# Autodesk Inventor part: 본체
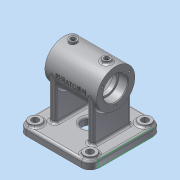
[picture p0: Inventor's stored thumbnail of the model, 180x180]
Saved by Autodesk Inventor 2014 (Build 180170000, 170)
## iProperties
Created: 2025-10
Part Number: 본체
Material: 알루미늄 6061
Document SubType Name: Modeling
Designer: dg
Density: 2.71 g/cm^3
Appearance: 알루미늄 - 평지
Mass: 505.532 g
Surface Area: 499.638 cm^2
Volume: 186.543 cm^3
Author: dg
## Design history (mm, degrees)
sketch "스케치1"
  geometry: L1 (-47, -47)-(47, -47); L2 (47, -47)-(47, 47); L3 (47, 47)-(-47, 47); L4 (-47, 47)-(-47, -47); L5 (-47, -47)-(47, 47); L6 (47, -47)-(-47, 47); 1 further point
  constraints: 12 end point, 2 midpoint, 2 parallel, 1 horizontal, 1 perpendicular
  dimensions: "d0" = 94 distance of L1.end L2.end; "d1" = 94 distance of L1.start L1.end
extrude "돌출1" new body sketch "스케치1" distance "d2" = 10; taper "d3" = 0 deg
sketch "스케치2"
  geometry: L1 (0, 47)-(0, -47) reference; L2 (66, -49.804)-(66, 56.223); L3 (66, 33.854)-(91, 33.854); L4 (91, 33.854)-(91, -34.146); L5 (91, -34.146)-(66, -34.146); L6 (82, 33.854)-(82, 21.854); L7 (82, 21.854)-(79.5, 21.854); L8 (79.5, 21.854)-(79.5, 16.258); L9 (79.5, 16.258)-(86, 5); L10 (86, 5)-(86, -5); L11 (86, -5)-(79.5, -16.258); L12 (79.5, -16.258)-(79.5, -22.146); L13 (79.5, -22.146)-(82, -22.146); L14 (82, -22.146)-(82, -34.146); 3 further points
  constraints: 26 end point, 6 parallel, 5 perpendicular, 4 point on line, 2 midpoint, 1 horizontal alignment
  dimensions: "d5" = 68 distance of L3.end L4.end; "d6" = 50 diameter of L4 L2; "d7" = 12 distance of L6.start L6.end; "d8" = 12 distance of L13.end L14.end; "d9" = 30 deg angle of L8 L9; "d10" = 30 deg angle of L12 L11; "d11" = 10 distance of L9.end L10.end; "d49" = 32 diameter of L6 L2; "d50" = 27 diameter of L8 L2; "d51" = 32 diameter of L14 L2; "d53" = 27 diameter of L12 L2; "d54" = 40 diameter of L10 L2; "d58" = 66 horizontal distance of L1.end L2.start
revolve "회전1" sketch "스케치2" stored, may be unused: angle "d12" = 90 deg
sketch "스케치3"
  geometry: L1 (-47, 47)-(-47, -47) reference; L2 (47, -47)-(47, 47) reference; L3 (-25, -29)-(25, -29); L4 (25, -29)-(25, -21); L5 (25, -21)-(-25, -21); L6 (-25, -21)-(-25, -29); L7 (-47, 0)-(47, 0); L8 (-25, 29)-(25, 29); L9 (25, 29)-(25, 21); L10 (25, 21)-(-25, 21); L11 (-25, 21)-(-25, 29); 4 further points
  constraints: 18 end point, 5 symmetric about line, 4 midpoint, 2 parallel, 1 horizontal, 1 perpendicular, 1 vertical alignment
  dimensions: "d13" = 8 distance of L5.end L3.start; "d14" = 50 distance of L3.start L3.end; "d15" = 21 distance between parallel lines of L7 L5
extrude "돌출2" join sketch "스케치3" stored distance "d16" = 10; taper "d17" = 0 deg
fillet "모깎기1" dims "d18" = 11
sketch "스케치4"
  geometry: C1 r 8 at (-36, -36); C2 r 8 at (36, -36); C3 r 8 at (36, 36); C4 r 8 at (-36, 36); A1 r 11 centre (-36, 36) between (-36, 47) and (-47, 36) reference; A2 r 11 centre (-36, -36) between (-47, -36) and (-36, -47) reference; A3 r 11 centre (36, -36) between (36, -47) and (47, -36) reference; A4 r 11 centre (36, 36) between (47, 36) and (36, 47) reference; 1 further point
  constraints: 4 centre point, 4 coincident
  dimensions: "d19" = 16 diameter of C1; "d20" = 16 diameter of C2; "d21" = 16 diameter of C3; "d22" = 16 diameter of C4
extrude "돌출3" join sketch "스케치4" distance "d23" = 3; taper "d24" = 0 deg
hole "구멍1" diameter "d27" = 9; stored, may be unused: countersink angle "d31" = 90 deg, drill point angle "d33" = 118 deg; dims "d25" = 10, "d26" = 10, "d28" = 6, "d29" = 4, "d30" = 2, "d32" = 8
sketch "스케치5"
  geometry: C1 r 16 at (0, 0) reference; 2 further points
hole "구멍2" sketch "스케치5" at (0, -20.5) diameter "d41" = 3.242; stored, may be unused: countersink angle "d45" = 90 deg, drill point angle "d47" = 118 deg; dims "d42" = 8, "d43" = 4, "d44" = 2, "d46" = 10
sketch "스케치6"
  geometry: L1 (0, 0)-(0, 10) reference; L2 (0, 0)-(72, 0) reference; L3 (72, 10)-(72, 0) reference; L4 (0, 10)-(72, 10) reference; 1 further point
node "작업 평면1"
sketch "스케치7"
  geometry: L1 (-25, 33.854)-(25, 33.854) reference; L2 (0, 33.854)-(0, 21.854); C1 r 5 at (0, 21.854); 1 further point
  constraints: 2 end point, 1 centre point, 1 coincident, 1 midpoint, 1 perpendicular
  dimensions: "d60" = 12 distance of L2.start L2.end; "d61" = 10 diameter of C1
extrude "돌출4" join sketch "스케치7" stored distance "d62" = 3; taper "d63" = 0 deg
sketch "스케치8"
  geometry: C1 r 5 at (0, 0) reference; C2 r 3.3 at (0, 0); 1 further point
  constraints: 1 centre point, 1 coincident
  dimensions: "d64" = 6.6 diameter of C2
extrude "돌출5" cut sketch "스케치8" distance "d65" = 2; taper "d66" = 0 deg
sketch "스케치9"
  geometry: C1 r 3.3 at (0, 0) reference; 2 further points
  constraints: 1 coincident
hole "구멍3" sketch "스케치9" at (0, 0) diameter "d67" = 5.188; stored, may be unused: countersink angle "d71" = 90 deg, drill point angle "d73" = 118 deg; dims "d68" = 15, "d69" = 4, "d70" = 2, "d72" = 17
node "작업 평면2"
sketch "스케치10"
  geometry: C1 r 6 at (0, 0); 1 further point
  constraints: 1 centre point, 1 coincident
  dimensions: "d75" = 12 diameter of C1
extrude "돌출6" join sketch "스케치10" stored distance "d76" = 2; taper "d77" = 0 deg
sketch "스케치11"
  geometry: C1 r 6 at (0, 0) reference; 1 further point
  constraints: 1 coincident
hole "구멍4" sketch "스케치11" at (0, 0) diameter "d78" = 5.188; stored, may be unused: countersink angle "d82" = 90 deg, drill point angle "d84" = 118 deg; dims "d79" = 20, "d80" = 4, "d81" = 2, "d83" = 10
sketch "스케치12"
  geometry: C1 r 10 at (0, 0); 1 further point
  constraints: 1 centre point, 1 coincident
  dimensions: "d85" = 20 diameter of C1
extrude "돌출7" cut sketch "스케치12" stored distance "d86" = 2; taper "d87" = 0 deg
fillet "모깎기2" dims "d88" = 0.3
chamfer "모따기1" distance "d89" = 1; stored, may be unused: second distance "d90" = 2, angle "d91" = 45 deg
fillet "모깎기3" dims "d92" = 3
fillet "모깎기4" dims "d93" = 3
fillet "모깎기5" dims "d94" = 3
fillet "모깎기6" dims "d95" = 3
fillet "모깎기7" dims "d96" = 3
fillet "모깎기8" dims "d97" = 3
node "작업 평면3"
sketch "스케치13"
  geometry: L1 (66, -35.854)-(66, 36.146) reference; 3 further points
  constraints: 1 horizontal alignment, 1 midpoint, 1 other
  dimensions: "d98" = 66 distance from line of point (0, 0.146) L1
feature "엠보싱1" sketch "스케치13" dims "d99" = 0.5, "d100" = 0
sketch "스케치14"
  geometry: L1 (-25, -34.146)-(25, -34.146) reference; L2 (0, -34.146)-(0, -22.146); C1 r 5 at (0, -22.146); 1 further point
  constraints: 2 end point, 1 centre point, 1 coincident, 1 midpoint, 1 perpendicular
  dimensions: "d101" = 12 distance of L2.start L2.end; "d102" = 10 diameter of C1
extrude "돌출8" join sketch "스케치14" stored distance "d103" = 2; taper "d104" = 0 deg
sketch "스케치15"
  geometry: C1 r 5 at (0, 0) reference; C2 r 3.3 at (0, 0); 1 further point
  constraints: 1 centre point, 1 coincident
  dimensions: "d105" = 6.6 diameter of C2
extrude "돌출9" cut sketch "스케치15" distance "d106" = 2; taper "d107" = 0 deg
sketch "스케치16"
  geometry: C1 r 3.3 at (0, 0) reference; 2 further points
  constraints: 1 coincident
hole "구멍5" sketch "스케치16" at (0, 0) diameter "d108" = 5.188; stored, may be unused: countersink angle "d112" = 90 deg, drill point angle "d114" = 118 deg; dims "d109" = 15, "d110" = 4, "d111" = 2, "d113" = 17
sketch "스케치17"
  geometry: 2 further points
hole "구멍6" sketch "스케치17" at (0, -20.5) diameter "d116" = 3.242; stored, may be unused: countersink angle "d120" = 90 deg, drill point angle "d122" = 118 deg; dims "d117" = 8, "d118" = 4, "d119" = 2, "d121" = 10
node "솔리드1"
pattern_linear "직사각형 패턴1" dims "d36" = 72, "d39" = 72
pattern_circular "원형 패턴1" dims angle "d56" = 360 deg
pattern_circular "원형 패턴2" dims angle "d124" = 360 deg
other parameters: "d59" = -94, "d74" = -38
